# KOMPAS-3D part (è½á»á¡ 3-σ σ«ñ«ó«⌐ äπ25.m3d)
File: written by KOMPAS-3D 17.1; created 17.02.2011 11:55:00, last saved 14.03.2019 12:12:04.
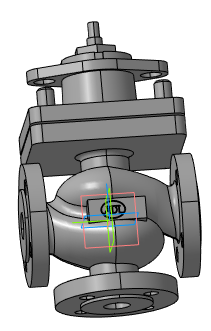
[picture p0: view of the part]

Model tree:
1. Плоскость XY
2. Плоскость ZX
3. Плоскость ZY
4. Ось X
5. Ось Y
6. Ось Z
7. Начало координат
8. Операция без истории:2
